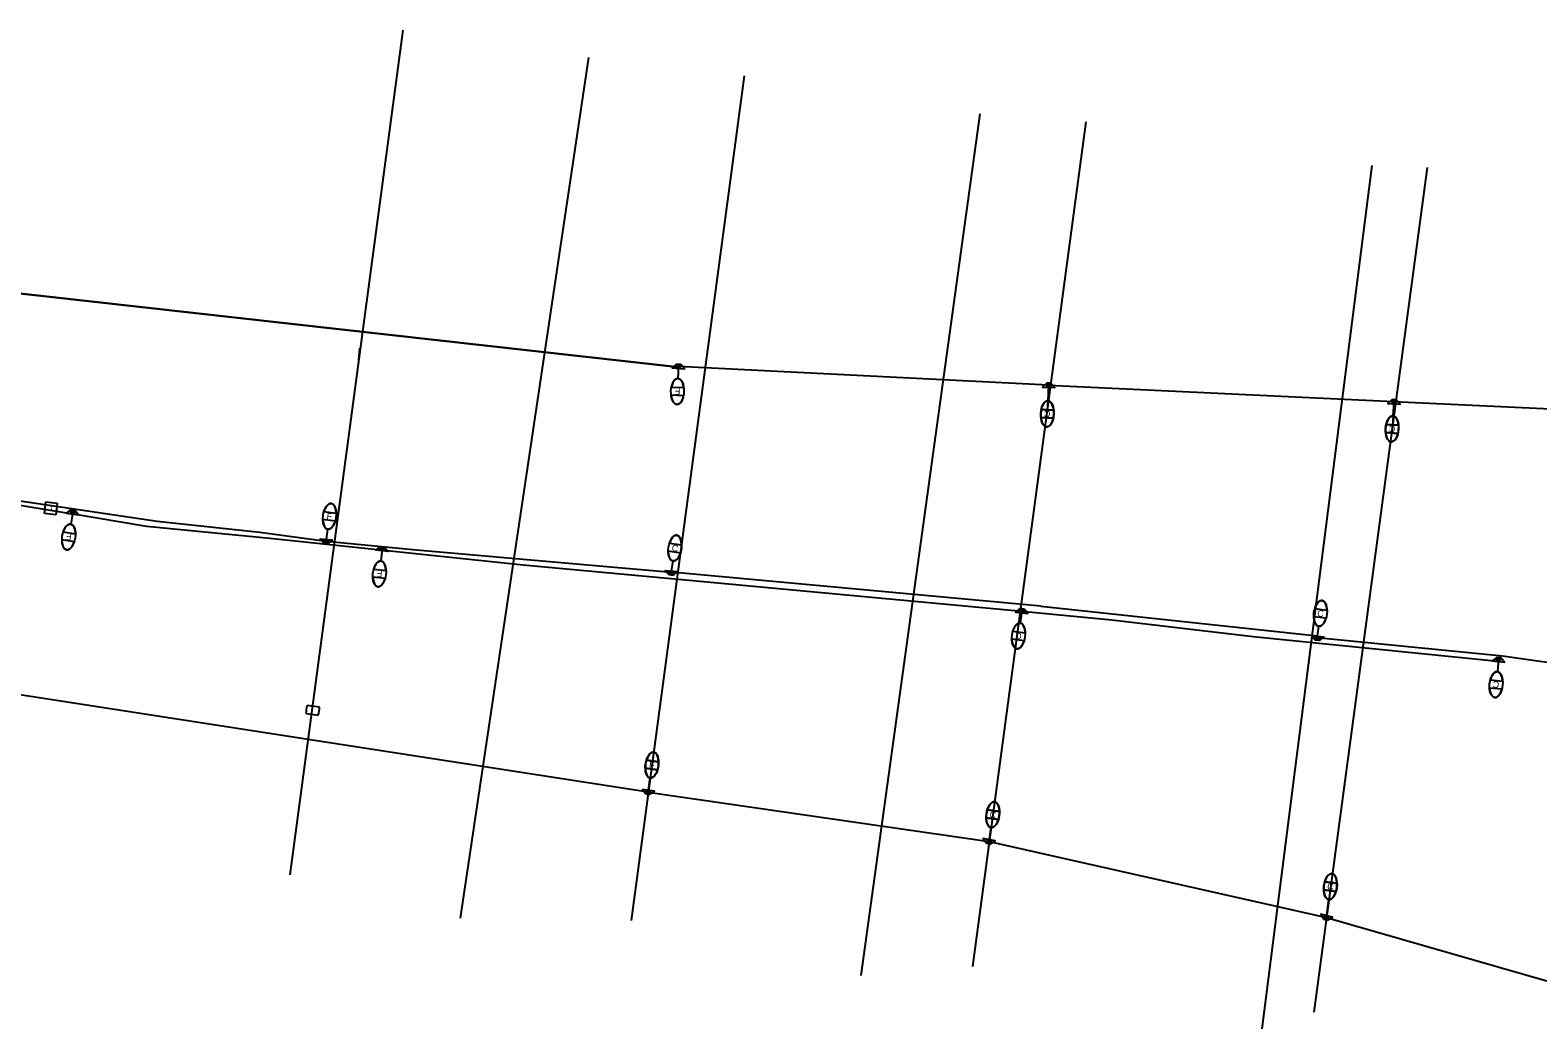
# Model space of a CAD drawing. Extents: x 915723 to 927758, y 636394 to 638609.
# Drawn here: x 925539 to 926458, y 636533 to 637142 of the extents above; entities that cross this region are included whole.
import ezdxf

# ---------------------------------------------------------------- set-up
doc = ezdxf.new("R2010")
doc.units = 0
for name, color, linetype in [('ConduitBM', 7, 'Continuous'), ('ConduitJB', 7, 'Continuous'), ('ConduitOT', 7, 'Continuous'), ('DrShaftConc', 7, 'Continuous'), ('Masonry_h', 7, 'Continuous'), ('Miscellaneous2', 7, 'Continuous'), ('PoleLight', 7, 'Continuous'), ('PullBox', 7, 'Continuous'), ('TextStructuresLabel', 7, 'Continuous')]:
    doc.layers.add(name, color=color, linetype=linetype)

msp = doc.modelspace()

# ---------------------------------------------------------------- linework, layer by layer
at = {"layer": 'ConduitBM'}
for p, q in [((926159.55, 636925.45), (925933.85, 636937.02)), ((926370.04, 636915.44), (926159.63, 636925.43)), ((926580.52, 636905.43), (926370.11, 636915.42)), ((925915.45, 636677.29), (924949.76, 636826.97)), ((926154.82, 636790.77), (925929.49, 636811.55)), ((926154.82, 636790.77), (926323.19, 636772.7)), ((925915.39, 636677.3), (926123.25, 636647.31)), ((926123.25, 636647.31), (926328.91, 636600.93)), ((926328.91, 636600.93), (926532.75, 636542.24))]:
    msp.add_line(p, q, dxfattribs=at)
for points in [[(925331.01, 636875.86), (925426.89, 636865.33), (925507.73, 636856.45), (925564.25, 636847.04)], [(925510.23, 636858.22), (925615.9, 636842.6), (925678.54, 636835.95), (925719.06, 636830.44)], [(925564.9, 636847.1), (925609.47, 636839.58), (925684.72, 636832.16), (925839.23, 636816.07), (925940.3, 636806.63)], [(925719.17, 636830.43), (925771.9, 636825.34), (925929.49, 636811.55)], [(925940.3, 636806.63), (926143.09, 636787.68)], [(926143.09, 636787.68), (926198.13, 636782.5), (926284.34, 636772.27), (926433.51, 636757.16)], [(926323.33, 636771.7), (926436.28, 636760.52), (926482.05, 636754)]]:
    msp.add_lwpolyline(points, dxfattribs=at)
at = {"layer": 'ConduitJB'}
msp.add_line((924983.84, 637042.69), (925933.76, 636936.47), dxfattribs=at)
at = {"layer": 'DrShaftConc'}
for p, q in [((925878.92, 637125.32), (925800.75, 636600.54)), ((926117.57, 637091.07), (926045.01, 636565.48)), ((926356.57, 637059.38), (926289.63, 636533.04)), ((925933.76, 636936.47), (924981.35, 637042.94))]:
    msp.add_line(p, q, dxfattribs=at)
at = {"layer": 'Masonry_h'}
for p, q in [((925765.85, 637142.01), (925696.76, 636626.99)), ((925973.98, 637114.09), (925904.89, 636599.07)), ((926182.12, 637086.17), (926113.03, 636571.15)), ((926390.25, 637058.25), (926321.17, 636543.22)), ((925739.3, 636948.07), (925738.5, 636938.1)), ((926159.35, 636922.87), (926158.87, 636912.88)), ((926159.35, 636922.87), (926158.87, 636912.88)), ((926369.89, 636912.88), (926369.41, 636902.89)), ((926369.89, 636912.88), (926369.41, 636902.89))]:
    msp.add_line(p, q, dxfattribs=at)
at = {"layer": 'Miscellaneous2'}
for p, q in [((926154.86, 636905.75), (926154.86, 636905.75)), ((926154.86, 636905.75), (926162.36, 636905.4)), ((926162.6, 636910.39), (926155.09, 636910.75)), ((926155.09, 636910.75), (926155.09, 636910.75)), ((926365.06, 636896.66), (926365.06, 636896.66)), ((926365.06, 636896.66), (926372.56, 636896.16)), ((926372.89, 636901.14), (926365.39, 636901.64)), ((926365.39, 636901.64), (926365.39, 636901.64)), ((925714.89, 636729.18), (925707.45, 636730.29)), ((925714.89, 636729.18), (925714.89, 636729.18)), ((925706.72, 636725.34), (925714.15, 636724.24)), ((925714.15, 636724.24), (925714.15, 636724.24)), ((925913.62, 636691.92), (925921.06, 636690.89)), ((925921.75, 636695.84), (925914.3, 636696.87)), ((925921.06, 636690.89), (925921.06, 636690.89)), ((925921.75, 636695.84), (925921.75, 636695.84)), ((926129.57, 636665.56), (926122.12, 636666.59)), ((926129.57, 636665.56), (926129.57, 636665.56)), ((926121.44, 636661.64), (926128.88, 636660.61)), ((926128.88, 636660.61), (926128.88, 636660.61)), ((926327.27, 636617.78), (926334.73, 636616.83)), ((926335.36, 636621.79), (926327.9, 636622.74)), ((926335.36, 636621.79), (926335.36, 636621.79)), ((926334.73, 636616.83), (926334.73, 636616.83))]:
    msp.add_line(p, q, dxfattribs=at)
for centre, major_axis, start_param, end_param in [((926158.73, 636908.07), (0.38, 7.91), 1.249648, 1.891946), ((926158.73, 636908.07), (0.38, 7.91), 4.391271, 5.033538), ((926158.73, 636908.07), (0.38, 7.91), 4.391241, 4.391271), ((926368.98, 636898.9), (0.53, 7.9), 1.249648, 1.891946), ((926368.98, 636898.9), (0.53, 7.9), 4.391271, 5.033538), ((926368.98, 636898.9), (0.53, 7.9), 4.391241, 4.391271), ((925710.8, 636727.26), (-1.17, -7.83), 4.391271, 5.033538), ((925710.8, 636727.26), (-1.17, -7.83), 4.391241, 4.391271), ((925710.8, 636727.26), (-1.17, -7.83), 1.249648, 1.891946), ((925917.68, 636693.88), (-1.08, -7.85), 4.391271, 5.033538), ((925917.68, 636693.88), (-1.08, -7.85), 4.391241, 4.391271), ((925917.68, 636693.88), (-1.08, -7.85), 1.249648, 1.891946), ((926125.5, 636663.6), (-1.08, -7.85), 4.391271, 5.033538), ((926125.5, 636663.6), (-1.08, -7.85), 4.391241, 4.391271), ((926125.5, 636663.6), (-1.08, -7.85), 1.249648, 1.891946), ((926331.31, 636619.79), (-1, -7.86), 4.391271, 5.033538), ((926331.31, 636619.79), (-1, -7.86), 4.391241, 4.391271), ((926331.31, 636619.79), (-1, -7.86), 1.249648, 1.891946)]:
    msp.add_ellipse(centre, major_axis=major_axis, ratio=0.5, start_param=start_param, end_param=end_param, dxfattribs=at)
at = {"layer": 'PoleLight'}
for p, q in [((925933.78, 636937.04), (925933.51, 636929.62)), ((925929.56, 636924.34), (925937.07, 636924.06)), ((926159.55, 636925.45), (926159.1, 636915.98)), ((925936.89, 636919.07), (925929.38, 636919.34)), ((926370.08, 636915.39), (926369.5, 636906.8)), ((926162.36, 636905.4), (926154.86, 636905.75)), ((926155.09, 636910.75), (926162.6, 636910.39)), ((926372.56, 636896.16), (926365.06, 636896.66)), ((926365.39, 636901.64), (926372.89, 636901.14)), ((925564.46, 636848.15), (925563.29, 636840.82)), ((925717.68, 636848.48), (925725.13, 636847.48)), ((925724.47, 636842.53), (925717.02, 636843.53)), ((925719.03, 636830.3), (925720.02, 636837.65)), ((925565.35, 636829.94), (925557.93, 636831.13)), ((925558.72, 636836.06), (925566.14, 636834.88)), ((925928.32, 636829.19), (925935.75, 636828.08)), ((925753.17, 636825.74), (925752.36, 636818.36)), ((925935.02, 636823.13), (925927.58, 636824.24)), ((925748.03, 636813.39), (925755.5, 636812.57)), ((925929.41, 636810.98), (925930.5, 636818.33)), ((925754.95, 636807.6), (925747.48, 636808.42)), ((926143.15, 636787.85), (926142.19, 636780.49)), ((926328.64, 636783.39), (926321.18, 636784.35)), ((926321.83, 636789.31), (926329.28, 636788.35)), ((926137.76, 636775.6), (926145.21, 636774.62)), ((926323.26, 636771.13), (926324.21, 636778.49)), ((926144.56, 636769.67), (926137.11, 636770.64)), ((926433.88, 636758.24), (926433.14, 636750.85)), ((926428.87, 636745.83), (926436.34, 636745.09)), ((926435.85, 636740.11), (926428.37, 636740.86)), ((925921.06, 636690.89), (925913.62, 636691.92)), ((925914.3, 636696.87), (925921.75, 636695.84)), ((925915.39, 636677.3), (925916.6, 636686.04)), ((926122.12, 636666.59), (926129.57, 636665.56)), ((926128.88, 636660.61), (926121.44, 636661.64)), ((926123.25, 636647.31), (926124.42, 636655.75)), ((926334.73, 636616.83), (926327.27, 636617.78)), ((926327.9, 636622.74), (926335.36, 636621.79)), ((926328.9, 636600.85), (926330.31, 636611.93))]:
    msp.add_line(p, q, dxfattribs=at)
for points in [[(925935.22, 636938.23), (925932.72, 636938.37), (925930.08, 636936.03), (925937.56, 636935.58)], [(926160.94, 636926.66), (926158.45, 636926.77), (926155.83, 636924.4), (926163.32, 636924.04)], [(926371.44, 636916.64), (926368.95, 636916.76), (926366.33, 636914.38), (926373.82, 636914.03)], [(925565.85, 636849.31), (925563.38, 636849.67), (925560.54, 636847.58), (925567.95, 636846.46)], [(925565.85, 636849.31), (925563.38, 636849.67), (925560.54, 636847.58), (925567.95, 636846.46)], [(925720.04, 636828.89), (925717.55, 636829.14), (925715.31, 636831.86), (925722.77, 636831.13)], [(925720.04, 636828.89), (925717.55, 636829.14), (925715.31, 636831.86), (925722.77, 636831.13)], [(925752.14, 636827.1), (925754.63, 636826.82), (925756.84, 636824.07), (925749.38, 636824.89)], [(925930.56, 636809.57), (925928.07, 636809.8), (925925.79, 636812.5), (925933.27, 636811.85)], [(925930.56, 636809.57), (925928.07, 636809.8), (925925.79, 636812.5), (925933.27, 636811.85)], [(926144.54, 636789.05), (926142.05, 636789.27), (926139.33, 636787.02), (926146.8, 636786.33)], [(926144.54, 636789.05), (926142.05, 636789.27), (926139.33, 636787.02), (926146.8, 636786.33)], [(926324.48, 636769.81), (926322, 636770.08), (926319.79, 636772.84), (926327.24, 636772.02)], [(926324.48, 636769.81), (926322, 636770.08), (926319.79, 636772.84), (926327.24, 636772.02)], [(926435.21, 636759.3), (926432.72, 636759.56), (926429.97, 636757.35), (926437.42, 636756.54)], [(926435.21, 636759.3), (926432.72, 636759.56), (926429.97, 636757.35), (926437.42, 636756.54)], [(925913.96, 636676.25), (925916.43, 636675.9), (925919.26, 636678.01), (925911.84, 636679.08)], [(926121.64, 636646.18), (926124.1, 636645.73), (926127.02, 636647.72), (926119.64, 636649.1)], [(926327.23, 636600), (926329.66, 636599.38), (926332.7, 636601.18), (926325.43, 636603.04)]]:
    msp.add_lwpolyline(points, close=True, dxfattribs=at)
for centre, radius in [((925933.78, 636937.04), 1.14), ((925933.78, 636937.04), 0.569), ((926159.54, 636925.45), 1.14), ((926370.04, 636915.44), 1.14), ((925564.46, 636848.15), 1.14), ((925564.46, 636848.15), 0.569), ((925719.03, 636830.3), 1.14), ((925719.03, 636830.3), 0.569), ((925753.17, 636825.74), 1.14), ((925753.17, 636825.74), 0.569), ((925929.41, 636810.98), 1.14), ((925929.41, 636810.98), 0.569), ((926143.15, 636787.85), 1.14), ((926143.15, 636787.85), 0.569), ((926323.26, 636771.13), 1.14), ((926323.26, 636771.13), 0.569), ((926433.88, 636758.24), 1.14), ((926433.88, 636758.24), 0.569), ((925915.44, 636677.32), 1.14), ((926123.17, 636647.19), 1.14), ((926328.91, 636600.92), 1.14)]:
    msp.add_circle(centre, radius, dxfattribs=at)
for centre, major_axis in [((925933.22, 636921.7), (0.29, 7.91)), ((926158.73, 636908.07), (0.38, 7.91)), ((926368.98, 636898.9), (0.53, 7.9)), ((925721.07, 636845.5), (-1.05, -7.85)), ((925562.03, 636833), (1.25, 7.82)), ((925931.67, 636826.16), (-1.17, -7.83)), ((925751.49, 636810.49), (0.86, 7.87)), ((926325.23, 636786.35), (-1.02, -7.85)), ((926141.16, 636772.63), (1.03, 7.85)), ((926432.36, 636742.97), (0.79, 7.88)), ((925917.68, 636693.88), (-1.08, -7.85)), ((926125.5, 636663.6), (-1.08, -7.85)), ((926331.31, 636619.79), (-1, -7.86))]:
    msp.add_ellipse(centre, major_axis=major_axis, ratio=0.5, dxfattribs=at)
for centre, major_axis, start_param, end_param in [((925933.22, 636921.7), (0.29, 7.91), 0, 0.847605), ((925933.22, 636921.7), (0.29, 7.91), 5.033538, 6.283185), ((925933.22, 636921.7), (0.29, 7.91), 0.847605, 1.249648), ((925933.22, 636921.7), (0.29, 7.91), 1.891945, 4.391241), ((926158.73, 636908.07), (0.38, 7.91), 0.847605, 1.249648), ((926158.73, 636908.07), (0.38, 7.91), 0, 0.847605), ((926158.73, 636908.07), (0.38, 7.91), 5.033538, 6.283185), ((926158.73, 636908.07), (0.38, 7.91), 1.891945, 4.391241), ((926368.98, 636898.9), (0.53, 7.9), 0.847605, 1.249648), ((926368.98, 636898.9), (0.53, 7.9), 0, 0.847605), ((926368.98, 636898.9), (0.53, 7.9), 5.033538, 6.283185), ((926368.98, 636898.9), (0.53, 7.9), 1.891945, 4.391241), ((925721.07, 636845.5), (-1.05, -7.85), 1.891945, 4.391241), ((925562.03, 636833), (1.25, 7.82), 0.847605, 1.249648), ((925562.03, 636833), (1.25, 7.82), 0, 0.847605), ((925562.03, 636833), (1.25, 7.82), 5.033538, 6.283185), ((925721.07, 636845.5), (-1.05, -7.85), 5.033538, 6.283185), ((925721.07, 636845.5), (-1.05, -7.85), 0, 0.847605), ((925721.07, 636845.5), (-1.05, -7.85), 0.847605, 1.249648), ((925562.03, 636833), (1.25, 7.82), 1.891945, 4.391241), ((925931.67, 636826.16), (-1.17, -7.83), 1.891945, 4.391241), ((925931.67, 636826.16), (-1.17, -7.83), 5.033538, 6.283185), ((925931.67, 636826.16), (-1.17, -7.83), 0, 0.847605), ((925931.67, 636826.16), (-1.17, -7.83), 0.847605, 1.249648), ((925751.49, 636810.49), (0.86, 7.87), 0.847605, 1.249648), ((925751.49, 636810.49), (0.86, 7.87), 0, 0.847605), ((925751.49, 636810.49), (0.86, 7.87), 5.033538, 6.283185), ((925751.49, 636810.49), (0.86, 7.87), 1.891945, 4.391241), ((926325.23, 636786.35), (-1.02, -7.85), 1.891945, 4.391241), ((926325.23, 636786.35), (-1.02, -7.85), 5.033538, 6.283185), ((926325.23, 636786.35), (-1.02, -7.85), 0.847605, 1.249648), ((926141.16, 636772.63), (1.03, 7.85), 0.847605, 1.249648), ((926141.16, 636772.63), (1.03, 7.85), 0, 0.847605), ((926141.16, 636772.63), (1.03, 7.85), 5.033538, 6.283185), ((926325.23, 636786.35), (-1.02, -7.85), 0, 0.847605), ((926141.16, 636772.63), (1.03, 7.85), 1.891945, 4.391241), ((926432.36, 636742.97), (0.79, 7.88), 0.847605, 1.249648), ((926432.36, 636742.97), (0.79, 7.88), 0, 0.847605), ((926432.36, 636742.97), (0.79, 7.88), 5.033538, 6.283185), ((926432.36, 636742.97), (0.79, 7.88), 1.891945, 4.391241), ((925917.68, 636693.88), (-1.08, -7.85), 1.891945, 4.391241), ((925917.68, 636693.88), (-1.08, -7.85), 5.033538, 6.283185), ((925917.68, 636693.88), (-1.08, -7.85), 0.847605, 1.249648), ((925917.68, 636693.88), (-1.08, -7.85), 0, 0.847605), ((926125.5, 636663.6), (-1.08, -7.85), 1.891945, 4.391241), ((926125.5, 636663.6), (-1.08, -7.85), 5.033538, 6.283185), ((926125.5, 636663.6), (-1.08, -7.85), 0, 0.847605), ((926125.5, 636663.6), (-1.08, -7.85), 0.847605, 1.249648), ((926331.31, 636619.79), (-1, -7.86), 1.891945, 4.391241), ((926331.31, 636619.79), (-1, -7.86), 5.033538, 6.283185), ((926331.31, 636619.79), (-1, -7.86), 0, 0.847605), ((926331.31, 636619.79), (-1, -7.86), 0.847605, 1.249648)]:
    msp.add_ellipse(centre, major_axis=major_axis, ratio=0.5, start_param=start_param, end_param=end_param, dxfattribs=at)
at = {"layer": 'PullBox'}
for p, q in [((925547.18, 636847.27), (925548, 636854.34)), ((925554.26, 636846.45), (925547.18, 636847.27)), ((925548, 636854.34), (925555.08, 636853.53)), ((925555.08, 636853.53), (925554.26, 636846.45))]:
    msp.add_line(p, q, dxfattribs=at)

# ---------------------------------------------------------------- texts
at = {"layer": 'ConduitOT'}
msp.add_text('J', height=2.85, rotation=353.4313, dxfattribs=at).set_placement((925550.01, 636849.09))
at = {"layer": 'TextStructuresLabel'}
for s, rotation, p in [('F', 177.91494, (925935.03, 636923.64)), ('C', 177.277, (926160.69, 636909.98)), ('C', 176.18254, (926370.98, 636900.77)), ('F', 352.35975, (925719.08, 636843.75)), ('F', 170.91478, (925564.07, 636834.7)), ('C', 351.5274, (925929.52, 636824.46)), ('F', 173.73347, (925753.44, 636812.29)), ('C', 352.62452, (926323.12, 636784.61)), ('C', 172.53392, (926143.27, 636774.37)), ('C', 174.31081, (926434.42, 636744.77)), ('F', 352.1399, (925915.69, 636692.14)), ('C', 352.1399, (926123.37, 636661.87)), ('C', 352.7524, (926329.2, 636618.04))]:
    msp.add_text(s, height=4, rotation=rotation, dxfattribs=at).set_placement(p)

doc.saveas('drawing.dxf')
